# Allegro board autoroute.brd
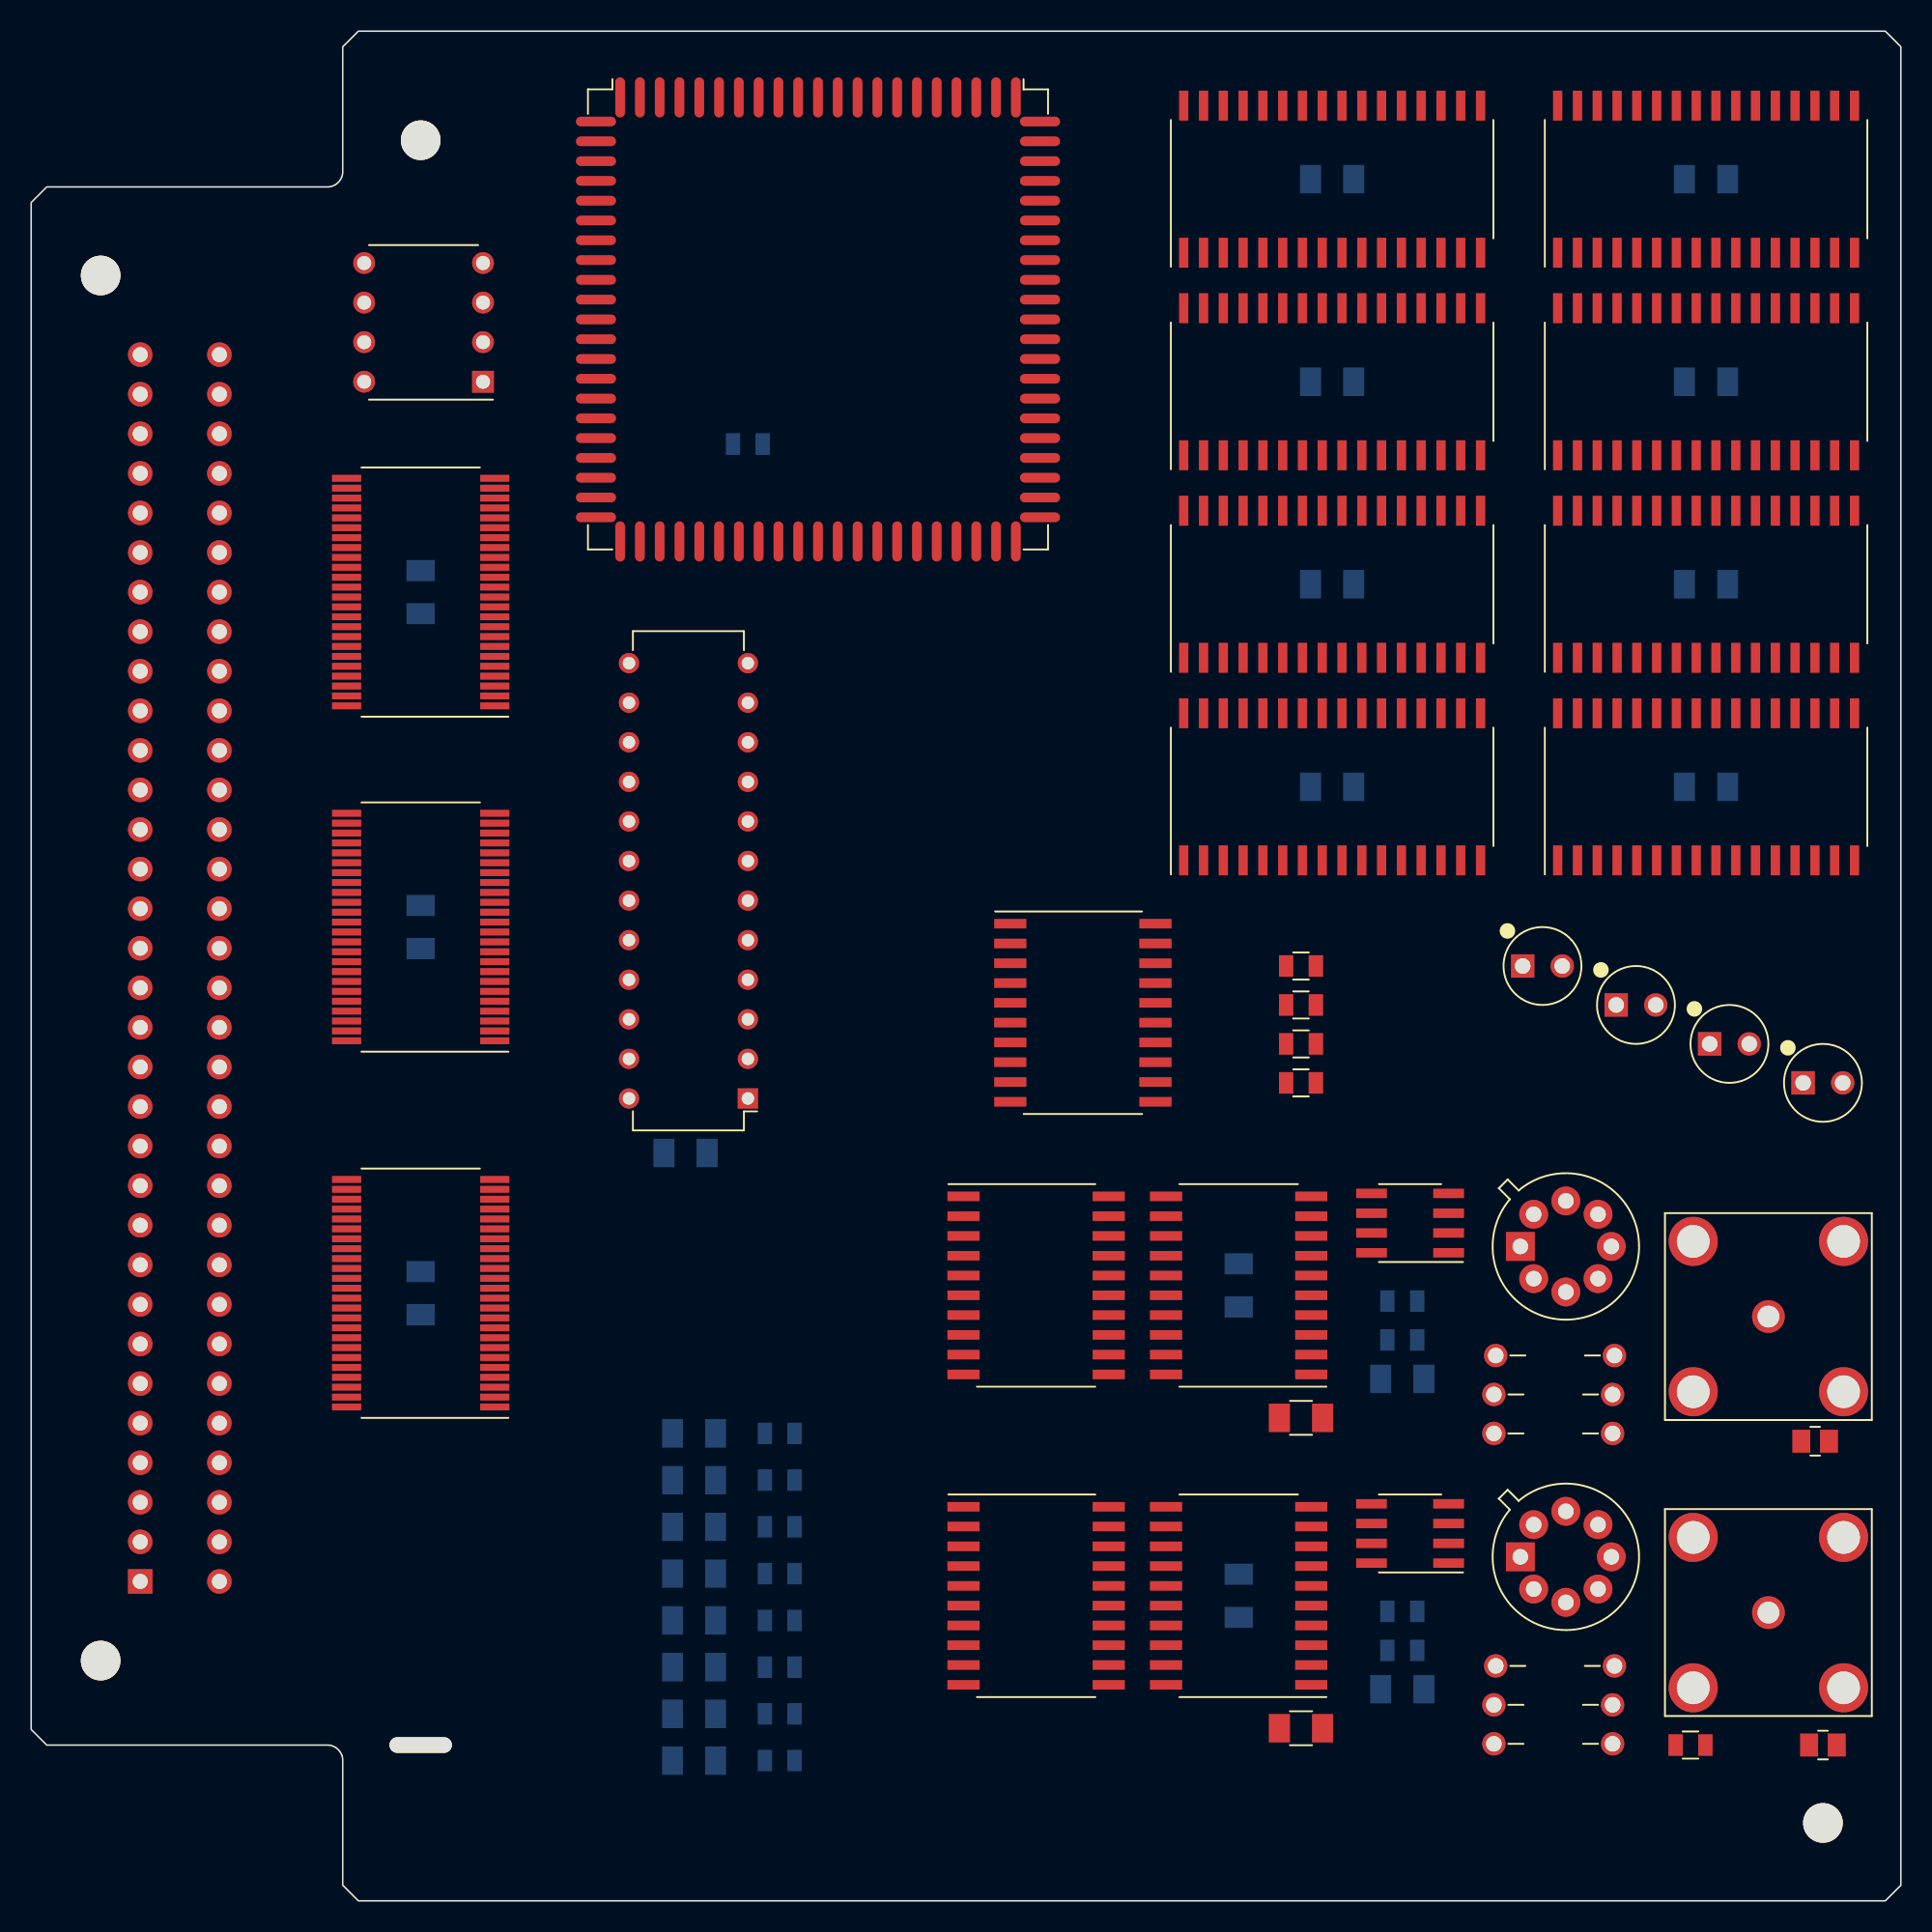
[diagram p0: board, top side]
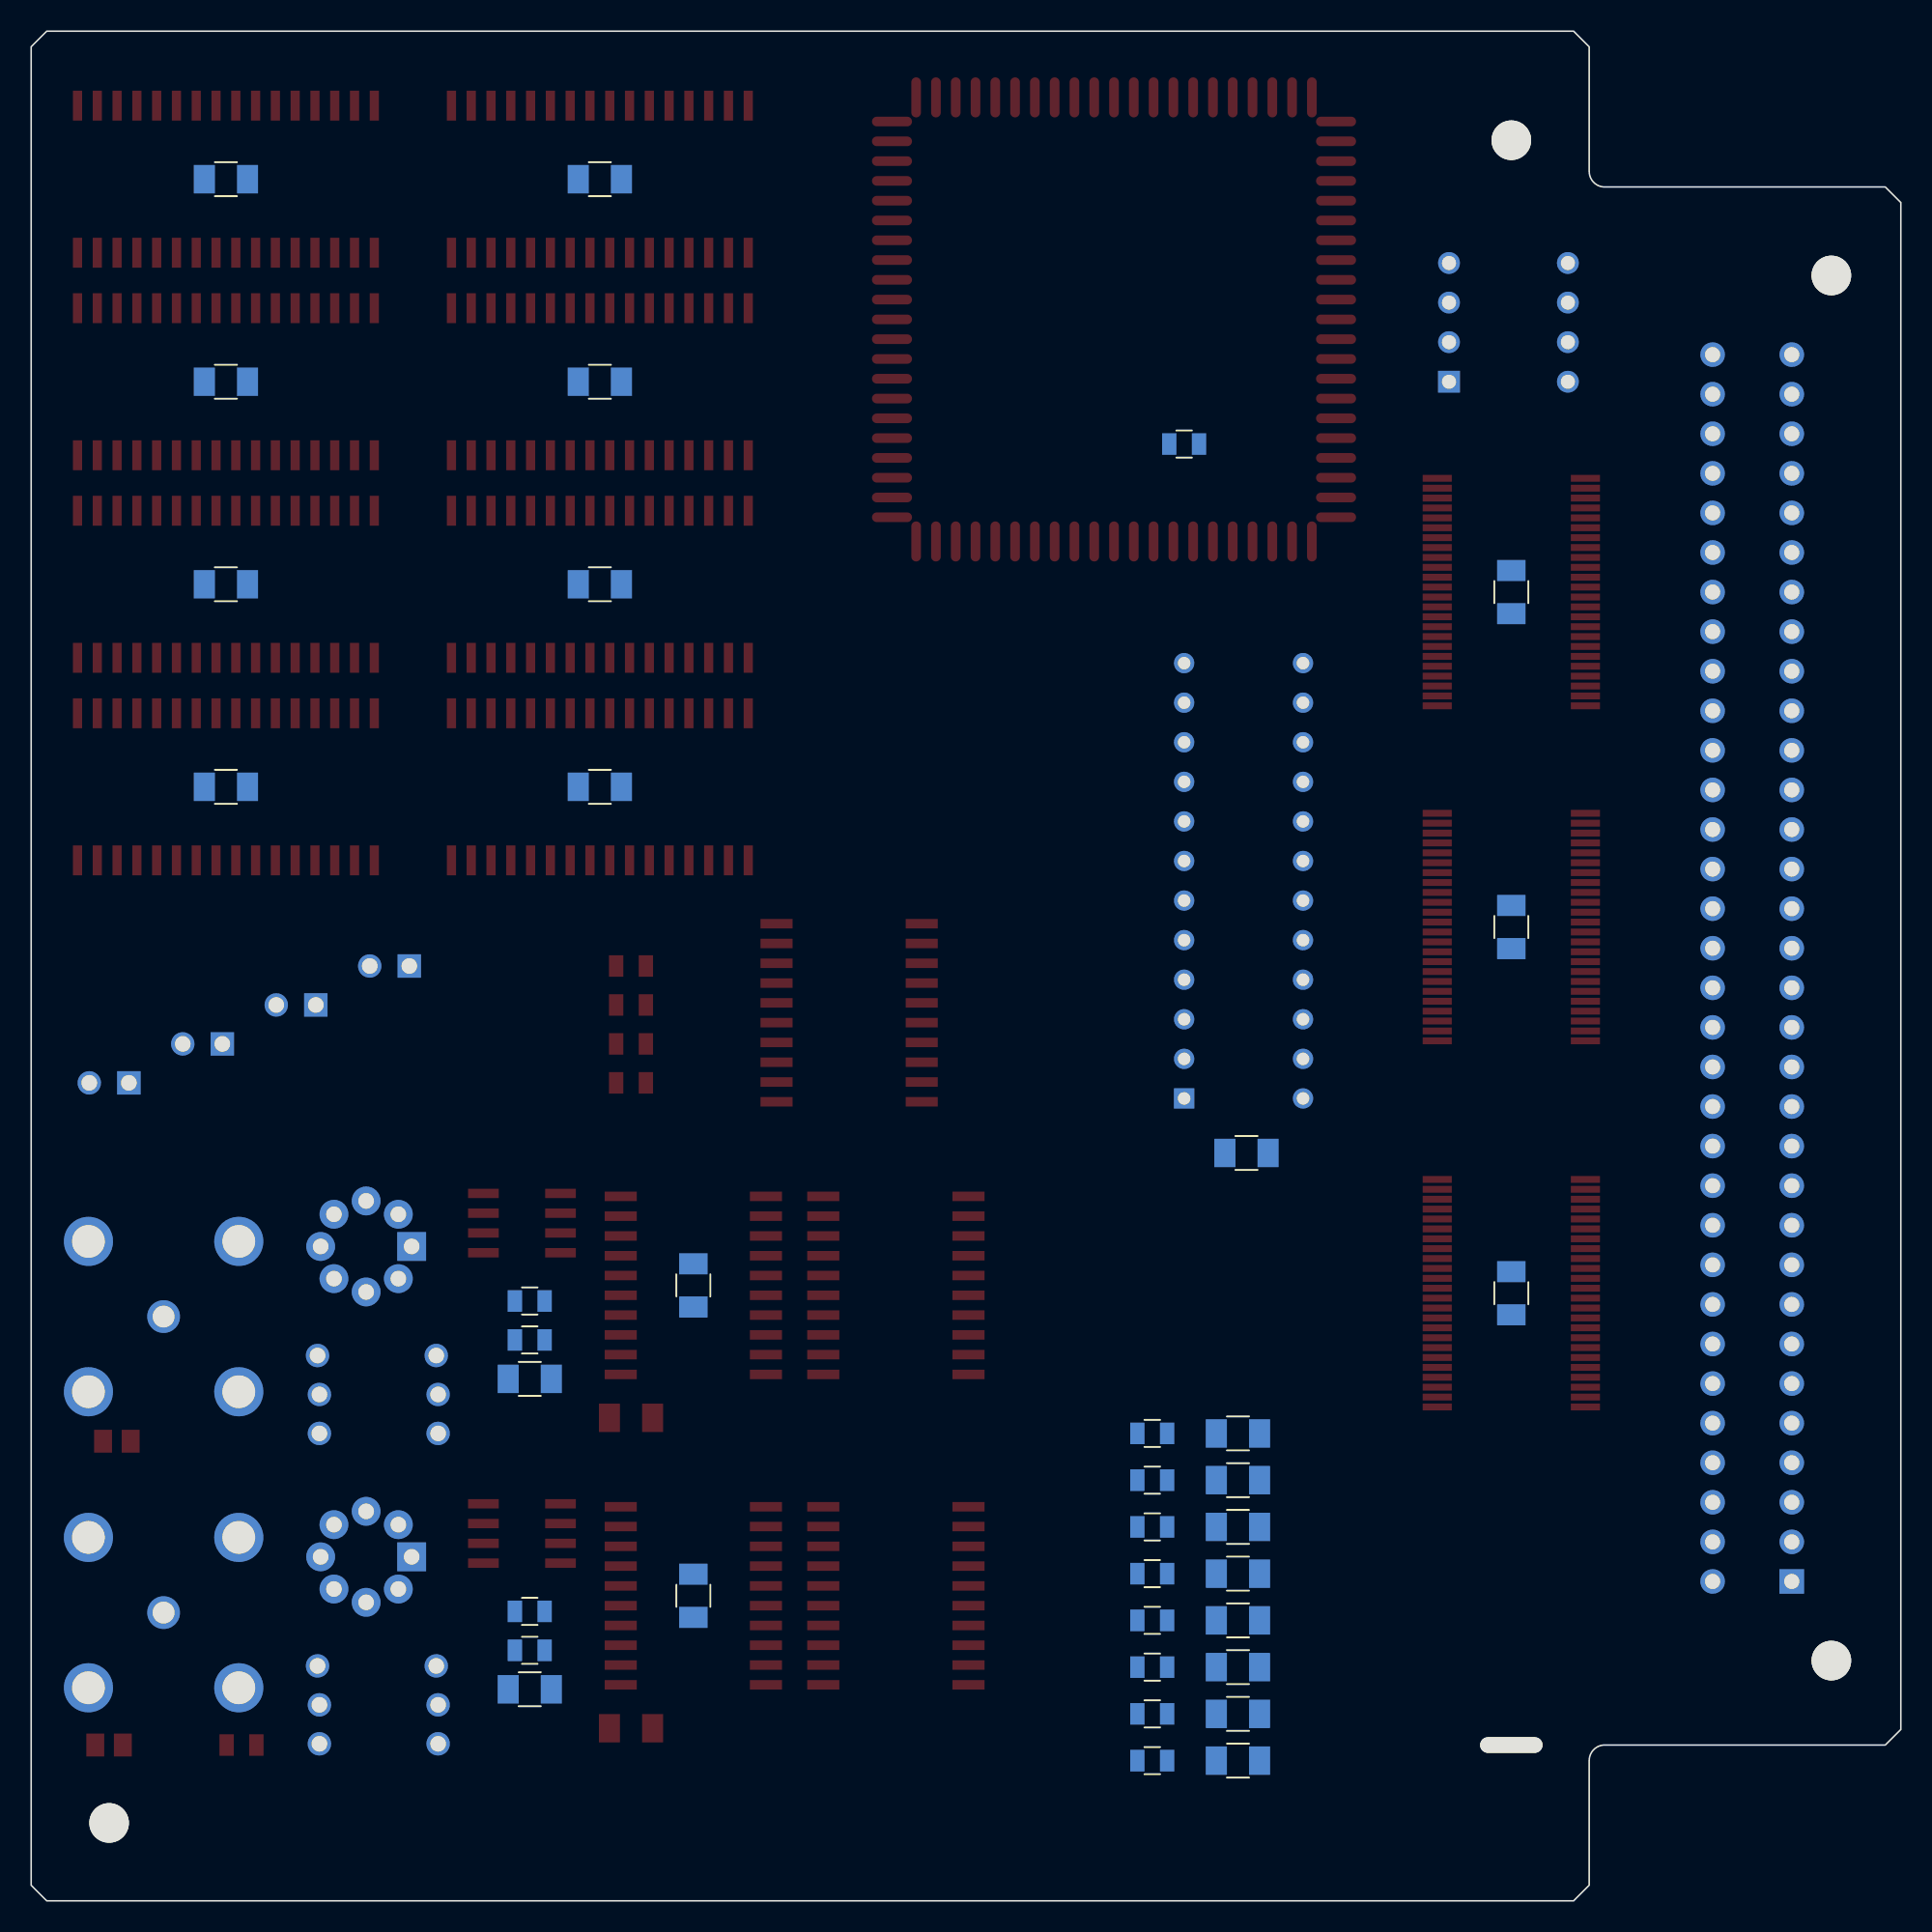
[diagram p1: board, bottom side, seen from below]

Outline 120 x 120 mm; copper layers: TOP, GND1, VCC1, VCC2, GND2, BOTTOM. Coordinates in mm from the lower left corner of the outline.

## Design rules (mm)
constraint set DEFAULT: min track width 0.15, pair gap 0.15
net group SYNC: nets VCLKA VCLKC
net group MEMORY[0..28]: nets MEMORY.RA0 MEMORY.RA1 MEMORY.RA2 MEMORY.RA3 MEMORY.RA4 MEMORY.RA5 MEMORY.RA6 MEMORY.RA7 MEMORY.RA8 MEMORY.RA9 MEMORY.RA10 MEMORY.RA11 MEMORY.RA12 MEMORY.RA13 MEMORY.RA14 MEMORY.RA15 MEMORY.RCS0 MEMORY.RCS1 MEMORY.RCS2 MEMORY.RCS3 MEMORY.RD0 MEMORY.RD1 MEMORY.RD2 MEMORY.RD3 MEMORY.RD4 MEMORY.RD5 MEMORY.RD6 MEMORY.RD7 MEMORY.RWE
net group POWER: nets AGND GND_EARTH V12N V+12
net group VDNETS: nets VD0 VD1 VD2 VD3 VD4 VD5 VD6 VD7
nets with their own width: min track width 0.4; nets GND VCC

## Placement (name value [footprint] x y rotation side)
C1  0.1uF  [CAPC3216X110N]  25 39 90 bottom
C2  0.1uF  [CAPC3216X110N]  42 48 0 bottom
C3  0.1uF  [CAPC3216X110N]  25 62.5 90 bottom
C4  0.1uF  [CAPC3216X110N]  25 84 90 bottom
C5  47PF  [CAPC2012X110N]  114.5 29.5 0 top
C6  47PF  [CAPC2012X110N]  115 10 0 top
C7  0.01u  [CAPC3216X110N]  81.5 31 0 top
C8  0.01u  [CAPC3216X110N]  77.5 39.5 90 bottom
C9  0.1u  [CAPC3216X110N]  88 33.5 180 bottom
C10  0.01u  [CAPC3216X110N]  81.5 11.08 0 top
C11  0.01u  [CAPC3216X110N]  77.5 19.58 90 bottom
C12  0.1u  [CAPC3216X110N]  88 13.58 180 bottom
C13  330p  [CAPC3216X110N]  42.55 12 180 bottom
C14  330p  [CAPC3216X110N]  42.55 18 180 bottom
C15  330p  [CAPC3216X110N]  42.55 24 180 bottom
C16  330p  [CAPC3216X110N]  42.55 30 180 bottom
C17  330p  [CAPC3216X110N]  42.55 9 180 bottom
C18  330p  [CAPC3216X110N]  42.55 15 180 bottom
C19  330p  [CAPC3216X110N]  42.55 21 180 bottom
C20  330p  [CAPC3216X110N]  42.55 27 180 bottom
C21  0.1uF  [CAPC3216X110N]  83.5 71.5 0 bottom
C22  0.1uF  [CAPC3216X110N]  107.5 71.5 0 bottom
C23  0.1uF  [CAPC3216X110N]  83.5 84.5 0 bottom
C24  0.1uF  [CAPC3216X110N]  107.5 84.5 0 bottom
C25  0.1uF  [CAPC3216X110N]  83.5 97.5 0 bottom
C26  0.1uF  [CAPC3216X110N]  107.5 97.5 0 bottom
C27  0.1uF  [CAPC3216X110N]  107.5 110.5 0 bottom
C28  0.1uF  [CAPC3216X110N]  83.5 110.5 0 bottom
D1  LED  [LEDRD254W00D500H860P]  97 60 0 top
D2  LED  [LEDRD254W00D500H860P]  103 57.5 0 top
D3  LED  [LEDRD254W00D500H860P]  109 55 0 top
D4  LED  [LEDRD254W00D500H860P]  115 52.5 0 top
J1  CON64  [DIN64]  7 20.5 0 top
J2  BNC  [CONNEX_112659]  111.5 37.5 0 top
J3  BNC  [CONNEX_112659]  111.5 18.5 0 top
L1  47u  [INDAD762W79L381D254P]  94 35 0 top
L2  47u  [INDAD762W79L381D254P]  94 15.08 0 top
L3  47u  [INDAD762W79L381D254P]  101.5 32.5 180 top
L4  47u  [INDAD762W79L381D254P]  101.5 30 180 top
L5  47u  [INDAD762W79L381D254P]  101.5 12.58 180 top
L6  47u  [INDAD762W79L381D254P]  101.5 10.08 180 top
NOREF  -  []  19.78 110.37 0 top
NOREF#2  -  []  25 10 0 top
NOREF#3  -  []  192.64 154.78 0 top
NOREF#4  -  []  25 10 0 top
NOREF#5  -  []  23 0 90 top
NOREF#6  -  []  119.52 119.48 0 top
NOREF#7  -  []  -74.06 -89.06 0 top
NOREF#8  -  []  20 6.38 0 top
NOREF#9  -  []  25 10 90 top
NOREF#10  -  [unnamed#2]  25 10 0 top
NOREF#11  -  []  25 10 90 top
NOREF#12  -  []  25 10 90 top
NOREF#13  -  []  115 5 90 top
NOREF#14  -  []  0 20.43 0 top
R1  150  [RESC2012X60N]  81.5 60 0 top
R2  150  [RESC2012X60N]  81.5 57.5 0 top
R3  150  [RESC2012X60N]  81.5 55 0 top
R4  150  [RESC2012X60N]  81.5 52.5 0 top
R5  2K  [RESC2012X60N]  46 93.5 0 bottom
R6  100  [RESC2012X60N]  88 38.5 180 bottom
R7  100  [RESC2012X60N]  88 36 180 bottom
R8  100  [RESC2012X60N]  88 18.58 180 bottom
R9  100  [RESC2012X60N]  88 16.08 180 bottom
R10  10K  [RESC2012X60N]  48.05 12 0 bottom
R11  10K  [RESC2012X60N]  48.05 18 0 bottom
R12  10K  [RESC2012X60N]  48.05 24 0 bottom
R13  10K  [RESC2012X60N]  48.05 30 0 bottom
R14  10K  [RESC2012X60N]  48.05 9 0 bottom
R15  10K  [RESC2012X60N]  48.05 15 0 bottom
R16  10K  [RESC2012X60N]  48.05 21 0 bottom
R17  10K  [RESC2012X60N]  48.05 27 0 bottom
R18  10K  [RESC2012X60N]  106.5 10 0 top
U1  FCT16245  [SOP63P1035X279-48N]  25 39 90 top
U2  20L10  [DIP763W46P254L3204H508Q24P]  46 51.5 90 top
U3  FCT16245  [SOP63P1035X279-48N]  25 62.5 90 top
U4  FCT16245  [SOP63P1035X279-48N]  25 84 90 top
U5  EPF8282A_LCC  [PLCC127P3022X3022X457-84N]  50.5 101.5 270 top
U6  74ACT574  [SOIC127P1034X264-20N]  67.5 57 270 top
U7  EPC1064  [DIP763W46P254L991H419Q8P]  29 97.5 90 top
U8  TLC5602A  [SOIC127P1034X264-20N]  77.5 39.5 90 top
U9  TLE2037A  [TO292P469H584-8P]  98.5 42 0 top
U10  DG419AK  [SOIC127P600X175-8N]  88.5 43.5 90 top
U11  TLC5602A  [SOIC127P1034X264-20N]  77.5 19.58 90 top
U12  TLE2037A  [TO292P469H584-8P]  98.5 22.08 0 top
U13  DG419AK  [SOIC127P600X175-8N]  88.5 23.58 90 top
U14  74ACT574  [SOIC127P1034X264-20N]  64.5 39.5 270 top
U15  74ACT574  [SOIC127P1034X264-20N]  64.5 19.58 270 top
U16  TC55B4257  [SOIC127P1032X265-32N]  83.5 71.5 0 top
U17  TC55B4257  [SOIC127P1032X265-32N]  83.5 84.5 0 top
U18  TC55B4257  [SOIC127P1032X265-32N]  83.5 97.5 0 top
U19  TC55B4257  [SOIC127P1032X265-32N]  83.5 110.5 0 top
U20  TC55B4257  [SOIC127P1032X265-32N]  107.5 71.5 0 top
U21  TC55B4257  [SOIC127P1032X265-32N]  107.5 84.5 0 top
U22  TC55B4257  [SOIC127P1032X265-32N]  107.5 97.5 0 top
U23  TC55B4257  [SOIC127P1032X265-32N]  107.5 110.5 0 top

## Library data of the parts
C1-C4 C13-C20 = CAP NP
C5 C7-C9 = CAP NP: room: CHAN1
C6 C10-C12 = CAP NP: room: CHAN2
C21-C28 = CAP NP: room: MEM
D1-D4 = PHOTODIODE_0
J1 = CON64
J2 = BNC: room: CHAN1
J3 = BNC: room: CHAN2
L1 L3 L4 = INDUCTOR: room: CHAN1
L2 L5 L6 = INDUCTOR: room: CHAN2
R1-R4 = R: room: LED
R5 R10-R17 = R
R6 R7 = R: room: CHAN1
R8 R9 R18 = R: room: CHAN2
U1 U3 U4 = FCT16245
U2 = 20L10: alternate symbols: (T:SOIC24;B:SOIC24_PE)
U5 = EPF8282A/LCC
U6 = 74ACT574: room: LED
U7 = EPC1064
U8 = TLC5602A: room: CHAN1
U9 = TLE2037A: room: CHAN1
U10 = DG419AK: room: CHAN1
U11 = TLC5602A: room: CHAN2
U12 = TLE2037A: room: CHAN2
U13 = DG419AK: room: CHAN2
U14 = 74ACT574: room: CHAN1
U15 = 74ACT574: room: CHAN2
U16-U23 = TC55B4257: room: MEM

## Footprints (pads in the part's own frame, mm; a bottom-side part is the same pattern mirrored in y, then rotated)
CAPC2012X110N
  rect 1.15x1.47 smd: 1(-0.885,0) 2(0.885,0)
CAPC3216X110N
  rect 1.35x1.82 smd: 1(-1.385,0) 2(1.385,0)
CONNEX_112659
  round 2.1 hole 1.4: 1(0,0)
  round 3.15 hole 2.1: 2(-4.825,4.825) 3(4.825,4.825) 4(4.825,-4.825) 5(-4.825,-4.825)
DIN64
  round 2.54 hole 2.794 unplated: (-2.54,83.82) (-2.54,-5.08)
  rect 1.575x1.575 hole 0.965: 1(0,0)
  round 1.575 hole 0.965: 2(0,2.54) 3(0,5.08) 4(0,7.62) 5(0,10.16) 6(0,12.7) 7(0,15.24) 8(0,17.78) 9(0,20.32) 10(0,22.86) 11(0,25.4) 12(0,27.94) 13(0,30.48) 14(0,33.02) 15(0,35.56) 16(0,38.1) 17(0,40.64) 18(0,43.18) 19(0,45.72) 20(0,48.26) 21(0,50.8) 22(0,53.34) 23(0,55.88) 24(0,58.42) 25(0,60.96) 26(0,63.5) 27(0,66.04) 28(0,68.58) 29(0,71.12) 30(0,73.66) 31(0,76.2) 32(0,78.74) 33(5.08,0) 34(5.08,2.54) 35(5.08,5.08) 36(5.08,7.62) 37(5.08,10.16) 38(5.08,12.7) 39(5.08,15.24) 40(5.08,17.78) 41(5.08,20.32) 42(5.08,22.86) 43(5.08,25.4) 44(5.08,27.94) 45(5.08,30.48) 46(5.08,33.02) 47(5.08,35.56) 48(5.08,38.1) 49(5.08,40.64) 50(5.08,43.18) 51(5.08,45.72) 52(5.08,48.26) 53(5.08,50.8) 54(5.08,53.34) 55(5.08,55.88) 56(5.08,58.42) 57(5.08,60.96) 58(5.08,63.5) 59(5.08,66.04) 60(5.08,68.58) 61(5.08,71.12) 62(5.08,73.66) 63(5.08,76.2) 64(5.08,78.74)
DIP763W46P254L991H419Q8P
  rect 1.4x1.4 hole 0.9: 1(0,0)
  round 1.4 hole 0.9: 2(2.54,0) 3(5.08,0) 4(7.62,0) 5(7.62,7.63) 6(5.08,7.63) 7(2.54,7.63) 8(0,7.63)
DIP763W46P254L3204H508Q24P
  rect 1.3x1.3 hole 0.8: 1(0,0)
  round 1.3 hole 0.8: 2(2.54,0) 3(5.08,0) 4(7.62,0) 5(10.16,0) 6(12.7,0) 7(15.24,0) 8(17.78,0) 9(20.32,0) 10(22.86,0) 11(25.4,0) 12(27.94,0) 13(27.94,7.63) 14(25.4,7.63) 15(22.86,7.63) 16(20.32,7.63) 17(17.78,7.63) 18(15.24,7.63) 19(12.7,7.63) 20(10.16,7.63) 21(7.62,7.63) 22(5.08,7.63) 23(2.54,7.63) 24(0,7.63)
INDAD762W79L381D254P
  round 1.5 hole 1: 1(0,0) 2(7.62,0)
LEDRD254W00D500H860P
  round 1.5 hole 1: A(1.27,0)
  rect 1.5x1.5 hole 1: C(-1.27,0)
PLCC127P3022X3022X457-84N
  oval 2.57x0.62 smd: 1(-14.25,0) 2(-14.25,-1.27) 3(-14.25,-2.54) 4(-14.25,-3.81) 5(-14.25,-5.08) 6(-14.25,-6.35) 7(-14.25,-7.62) 8(-14.25,-8.89) 9(-14.25,-10.16) 10(-14.25,-11.43) 11(-14.25,-12.7) 33(14.25,-12.7) 34(14.25,-11.43) 35(14.25,-10.16) 36(14.25,-8.89) 37(14.25,-7.62) 38(14.25,-6.35) 39(14.25,-5.08) 40(14.25,-3.81) 41(14.25,-2.54) 42(14.25,-1.27) 43(14.25,0) 44(14.25,1.27) 45(14.25,2.54) 46(14.25,3.81) 47(14.25,5.08) 48(14.25,6.35) 49(14.25,7.62) 50(14.25,8.89) 51(14.25,10.16) 52(14.25,11.43) 53(14.25,12.7) 75(-14.25,12.7) 76(-14.25,11.43) 77(-14.25,10.16) 78(-14.25,8.89) 79(-14.25,7.62) 80(-14.25,6.35) 81(-14.25,5.08) 82(-14.25,3.81) 83(-14.25,2.54) 84(-14.25,1.27)
  oval 0.62x2.57 smd: 12(-12.7,-14.25) 13(-11.43,-14.25) 14(-10.16,-14.25) 15(-8.89,-14.25) 16(-7.62,-14.25) 17(-6.35,-14.25) 18(-5.08,-14.25) 19(-3.81,-14.25) 20(-2.54,-14.25) 21(-1.27,-14.25) 22(0,-14.25) 23(1.27,-14.25) 24(2.54,-14.25) 25(3.81,-14.25) 26(5.08,-14.25) 27(6.35,-14.25) 28(7.62,-14.25) 29(8.89,-14.25) 30(10.16,-14.25) 31(11.43,-14.25) 32(12.7,-14.25) 54(12.7,14.25) 55(11.43,14.25) 56(10.16,14.25) 57(8.89,14.25) 58(7.62,14.25) 59(6.35,14.25) 60(5.08,14.25) 61(3.81,14.25) 62(2.54,14.25) 63(1.27,14.25) 64(0,14.25) 65(-1.27,14.25) 66(-2.54,14.25) 67(-3.81,14.25) 68(-5.08,14.25) 69(-6.35,14.25) 70(-7.62,14.25) 71(-8.89,14.25) 72(-10.16,14.25) 73(-11.43,14.25) 74(-12.7,14.25)
RESC2012X60N
  rect 0.92x1.38 smd: 1(-0.955,0) 2(0.955,0)
SOIC127P600X175-8N
  rect 0.6x1.97 smd: 1(-1.905,-2.475) 2(-0.635,-2.475) 3(0.635,-2.475) 4(1.905,-2.475) 5(1.905,2.475) 6(0.635,2.475) 7(-0.635,2.475) 8(-1.905,2.475)
SOIC127P1032X265-32N
  rect 0.59x1.92 smd: 1(-9.525,-4.72) 2(-8.255,-4.72) 3(-6.985,-4.72) 4(-5.715,-4.72) 5(-4.445,-4.72) 6(-3.175,-4.72) 7(-1.905,-4.72) 8(-0.635,-4.72) 9(0.635,-4.72) 10(1.905,-4.72) 11(3.175,-4.72) 12(4.445,-4.72) 13(5.715,-4.72) 14(6.985,-4.72) 15(8.255,-4.72) 16(9.525,-4.72) 17(9.525,4.72) 18(8.255,4.72) 19(6.985,4.72) 20(5.715,4.72) 21(4.445,4.72) 22(3.175,4.72) 23(1.905,4.72) 24(0.635,4.72) 25(-0.635,4.72) 26(-1.905,4.72) 27(-3.175,4.72) 28(-4.445,4.72) 29(-5.715,4.72) 30(-6.985,4.72) 31(-8.255,4.72) 32(-9.525,4.72)
SOIC127P1034X264-20N
  rect 0.61x2.06 smd: 1(-5.715,-4.66) 2(-4.445,-4.66) 3(-3.175,-4.66) 4(-1.905,-4.66) 5(-0.635,-4.66) 6(0.635,-4.66) 7(1.905,-4.66) 8(3.175,-4.66) 9(4.445,-4.66) 10(5.715,-4.66) 11(5.715,4.66) 12(4.445,4.66) 13(3.175,4.66) 14(1.905,4.66) 15(0.635,4.66) 16(-0.635,4.66) 17(-1.905,4.66) 18(-3.175,4.66) 19(-4.445,4.66) 20(-5.715,4.66)
SOP63P1035X279-48N
  rect 0.44x1.87 smd: 1(-7.302,-4.755) 2(-6.668,-4.755) 3(-6.032,-4.755) 4(-5.398,-4.755) 5(-4.762,-4.755) 6(-4.128,-4.755) 7(-3.492,-4.755) 8(-2.858,-4.755) 9(-2.222,-4.755) 10(-1.588,-4.755) 11(-0.952,-4.755) 12(-0.318,-4.755) 13(0.318,-4.755) 14(0.952,-4.755) 15(1.588,-4.755) 16(2.222,-4.755) 17(2.858,-4.755) 18(3.492,-4.755) 19(4.128,-4.755) 20(4.762,-4.755) 21(5.398,-4.755) 22(6.032,-4.755) 23(6.668,-4.755) 24(7.302,-4.755) 25(7.302,4.755) 26(6.668,4.755) 27(6.032,4.755) 28(5.398,4.755) 29(4.762,4.755) 30(4.128,4.755) 31(3.492,4.755) 32(2.858,4.755) 33(2.222,4.755) 34(1.588,4.755) 35(0.952,4.755) 36(0.318,4.755) 37(-0.318,4.755) 38(-0.952,4.755) 39(-1.588,4.755) 40(-2.222,4.755) 41(-2.858,4.755) 42(-3.492,4.755) 43(-4.128,4.755) 44(-4.762,4.755) 45(-5.398,4.755) 46(-6.032,4.755) 47(-6.668,4.755) 48(-7.302,4.755)
TO292P469H584-8P
  rect 1.85x1.85 hole 1: 1(-2.921,0)
  round 1.85 hole 1: 2(-2.066,-2.066) 3(0,-2.921) 4(2.066,-2.066) 5(2.921,0) 6(2.066,2.066) 7(0,2.921) 8(-2.066,2.066)
unnamed#2
  round 2.54 hole 2.794 unplated: (0,103) (90,-5)
  oval 4x1 hole 5x1.5 unplated: (0,0)

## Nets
AGND: C8.2 C9.2 C11.2 C12.2 J1.34 J1.35 J1.36 U8.3 U8.7 U8.10 U10.3 U11.3 U11.7 U11.10 U13.3
GND: C1.2 C2.2 C3.2 C4.2 C7.2 C10.2 C13.2 C14.2 C15.2 C16.2 C17.2 C18.2 C19.2 C20.2 C21.2 C22.2 C23.2 C24.2 C25.2 C26.2 C27.2 C28.2 J1.1 J1.2 J1.3 J1.33 R18.2 U1.4 U1.10 U1.15 U1.21 U1.24 U1.25(G\) U1.28 U1.34 U1.39 U1.45 U2.11 U2.12 U2.13 U3.4 U3.10 U3.15 U3.21 U3.24 U3.25(G\) U3.28 U3.34 U3.39 U3.45 U4.1 U4.4 U4.10 U4.15 U4.21 U4.28 U4.34 U4.39 U4.45 U4.48 U5.5 U5.26 U5.47 U5.53 U5.68 U5.74 U5.75 U6.1 U6.10 U7.5 U8.1 U8.20 U11.1 U11.20 U14.1 U14.10 U15.1 U15.10 U16.9 U16.25 U16.27 U17.9 U17.25 U17.27 U18.9 U18.25 U18.27 U19.9 U19.25 U19.27 U20.9 U20.25 U20.27 U21.9 U21.25 U21.27 U22.9 U22.25 U22.27 U23.9 U23.25 U23.27
GND_EARTH: C5.2 C6.2 J2.2 J2.3 J2.4 J2.5(GND5) J3.2 J3.3 J3.4 J3.5(GND5)
V12N: J1.31 J1.32 U9.4(V-) U10.7 U12.4(V-) U13.7
VCC: C1.1 C2.1 C3.1 C4.1 C7.1 C10.1 C21.1 C22.1 C23.1 C24.1 C25.1 C26.1 C27.1 C28.1 D1.A D2.A D3.A D4.A J1.29 J1.30 J1.62 L4.1 L6.1 U1.7 U1.18 U1.31 U1.42 U2.24(VCC) U3.7 U3.18 U3.31 U3.42 U4.7 U4.18 U4.31 U4.42 U5.17 U5.38 U5.59 U5.80 U6.20 U7.7 U7.8 U8.2 U8.9(VD2) U11.2 U11.9(VD2) U14.20 U15.20 U16.8 U16.24 U17.8 U17.24 U18.8 U18.24 U19.8 U19.24 U20.8 U20.24 U21.8 U21.24 U22.8 U22.24 U23.8 U23.24
A0: J1.54 U4.36
A1: J1.55 U4.35
A2: J1.56 U4.33
A3: J1.57 U4.32
A4: J1.58 U4.30
A5: J1.59 U4.29
A6: J1.60 U4.27
A7: J1.61 U4.26
A8: J1.13 U3.47
A9: J1.14 U3.46
A10: J1.15 U3.44
A11: J1.16 U3.43
A12: J1.17 U3.41
A13: J1.18 U3.40
A14: J1.19 U3.38
A15: J1.20 U3.37
A16: J1.37 U1.47
A17: J1.38 U1.46
A18: J1.39 U1.44 U2.6
A19: J1.40 U1.43 U2.5
A20: J1.41 U1.41 U2.4
A21: J1.42 U1.40 U2.3
A22: J1.43 U1.38 U2.2
A23: J1.44 U1.37 U2.1
AEN: J1.47 U2.8
BA0: U1.13 U3.13 U4.2 U5.6
BA1: U1.14 U3.14 U4.3 U5.7
BA2: U1.16 U3.16 U4.5 U5.8
BA3: U1.17 U3.17 U4.6 U5.9
BA4: U1.19 U3.19 U4.8
BA5: U1.20 U3.20 U4.9
BA6: U1.22 U3.22 U4.11
BA7: U1.23 U3.23 U4.12
BD0: U4.23 U5.25
BD1: U4.22 U5.24
BD2: U4.20 U5.23
BD3: U4.19 U5.22
BD4: U4.17 U5.21
BD5: U4.16 U5.20
BD6: U4.14 U5.19
BD7: U4.13 U5.18
BD8: U1.12 U3.2
BD9: U1.11 U3.3
BD10: U1.9 U3.5
BD11: U1.8 U3.6
BD12: U1.6 U3.8
BD13: U1.5 U3.9
BD14: U1.3 U3.11
BD15: U1.2 U3.12
BNC2: C5.1 J2.1 L1.2
BNC3: C6.1 J3.1 L2.2
BRD: U2.16 U5.73
BRESET: U2.15 U5.12
BWR: U2.17 U5.54
D0: J1.28 U3.26 U4.37
D1: J1.27 U3.27 U4.38
D2: J1.26 U3.29 U4.40
D3: J1.25 U3.30 U4.41
D4: J1.24 U3.32 U4.43
D5: J1.23 U3.33 U4.44
D6: J1.22 U3.35 U4.46
D7: J1.21 U3.36 U4.47
D8: J1.4 U1.36
D9: J1.5 U1.35
D10: J1.6 U1.33
D11: J1.7 U1.32
D12: J1.8 U1.30
D13: J1.9 U1.29
D14: J1.10 U1.27
D15: J1.11 U1.26
DATA: U5.14 U7.1
DCLK: U5.10 U7.2
DDIR: U1.48 U2.20 U3.48 U4.25(G\)
DEN: U1.1 U2.21 U4.24
DHEN: U2.22 U3.1
FPGA: U2.18 U5.30
GAIN: U5.28 U10.6 U13.6
HS: U2.19 U5.29
LED1: D1.C(CATHODE) R1.2
LED2: D2.C(CATHODE) R2.2
LED3: D3.C(CATHODE) R3.2
LED4: D4.C(CATHODE) R4.2
MCLK: J1.52 U5.31
MEMORY.RA0: U5.79 U16.5 U17.5 U18.5 U19.5 U20.5 U21.5 U22.5 U23.5
MEMORY.RA1: U5.78 U16.4 U17.4 U18.4 U19.4 U20.4 U21.4 U22.4 U23.4
MEMORY.RA2: U5.77 U16.3 U17.3 U18.3 U19.3 U20.3 U21.3 U22.3 U23.3
MEMORY.RA3: U5.76 U16.2 U17.2 U18.2 U19.2 U20.2 U21.2 U22.2 U23.2
MEMORY.RA4: U5.71 U16.32 U17.32 U18.32 U19.32 U20.32 U21.32 U22.32 U23.32
MEMORY.RA5: U5.70 U16.31 U17.31 U18.31 U19.31 U20.31 U21.31 U22.31 U23.31
MEMORY.RA6: U5.69 U16.30 U17.30 U18.30 U19.30 U20.30 U21.30 U22.30 U23.30
MEMORY.RA7: U5.67 U16.29 U17.29 U18.29 U19.29 U20.29 U21.29 U22.29 U23.29
MEMORY.RA8: U5.66 U16.28 U17.28 U18.28 U19.28 U20.28 U21.28 U22.28 U23.28
MEMORY.RA9: U5.65 U16.22 U17.22 U18.22 U19.22 U20.22 U21.22 U22.22 U23.22
MEMORY.RA10: U5.64 U16.21 U17.21 U18.21 U19.21 U20.21 U21.21 U22.21 U23.21
MEMORY.RA11: U5.63 U16.20 U17.20 U18.20 U19.20 U20.20 U21.20 U22.20 U23.20
MEMORY.RA12: U5.62 U16.19 U17.19 U18.19 U19.19 U20.19 U21.19 U22.19 U23.19
MEMORY.RA13: U5.61 U16.18 U17.18 U18.18 U19.18 U20.18 U21.18 U22.18 U23.18
MEMORY.RA14: U5.60 U16.15 U17.15 U18.15 U19.15 U20.15 U21.15 U22.15 U23.15
MEMORY.RA15: U5.58 U16.14 U17.14 U18.14 U19.14 U20.14 U21.14 U22.14 U23.14
MEMORY.RCS0: U5.51 U16.6 U17.6
MEMORY.RCS1: U5.50 U18.6 U19.6
MEMORY.RCS2: U5.49 U20.6 U21.6
MEMORY.RCS3: U5.48 U22.6 U23.6
MEMORY.RD0: U5.81 U16.7 U18.7 U20.7 U22.7
MEMORY.RD1: U5.82 U16.10 U18.10 U20.10 U22.10
MEMORY.RD2: U5.83 U16.23 U18.23 U20.23 U22.23
MEMORY.RD3: U5.84 U16.26 U18.26 U20.26 U22.26
MEMORY.RD4: U5.1 U17.7 U19.7 U21.7 U23.7
MEMORY.RD5: U5.2 U17.10 U19.10 U21.10 U23.10
MEMORY.RD6: U5.3 U17.23 U19.23 U21.23 U23.23
MEMORY.RD7: U5.4 U17.26 U19.26 U21.26 U23.26
MEMORY.RWE: U5.56 U16.11(W\E\) U17.11(W\E\) U18.11(W\E\) U19.11(W\E\) U20.11(W\E\) U21.11(W\E\) U22.11(W\E\) U23.11(W\E\)
MRD: J1.46 U2.9
MWR: J1.45 U2.10
N00036_DATA_DAAMP: L4.2 R6.1 R7.1 U8.5 U8.8 U10.5(VL)
N00036_DATA_DAAMP1: L6.2 R8.1 R9.1 U11.5 U11.8 U13.5(VL)
N00038_DATA_DAAMP: C8.1 L3.2 U8.4
N00038_DATA_DAAMP1: C11.1 L5.2 U11.4
N00044_DATA_DAAMP: U9.2 U10.1
N00044_DATA_DAAMP1: U12.2 U13.1
N00060_DATA_DAAMP: U8.6 U9.3
N00060_DATA_DAAMP1: U11.6 U12.3
N282866_DATA_DAAMP: R6.2 U10.8
N282866_DATA_DAAMP1: R8.2 U13.8
N282912_DATA_DAAMP: R7.2 U10.2
N282912_DATA_DAAMP1: R9.2 U13.2
NCS: U5.11 U7.4
OE: U5.32 U7.3(OE)
OUTA: L1.1 U9.6
OUTB: L2.1 U12.6
Q0: R1.1 U6.18
Q1: R2.1 U6.16
Q2: R3.1 U6.14
Q3: R4.1 U6.12(Q8)
RDY: J1.50 U2.23
RESET: J1.53 U5.15
SEL: U2.14 U5.13
V+12: C9.1 C12.1 J1.63 J1.64 U9.7 U10.4 U12.7 U13.4
VCLKA: U5.34 U8.11 U14.11
VCLKC: R5.2 U11.11 U15.11
VD0: R13.2 U5.39 U6.2 U14.2 U15.2
VD1: R17.2 U5.40 U6.3 U14.3 U15.3
VD2: R12.2 U5.41 U6.4 U14.4 U15.4
VD3: R16.2 U5.42 U6.5 U14.5 U15.5
VD4: R11.2 U5.43 U6.6 U14.6 U15.6
VD5: R15.2 U5.44 U6.7 U14.7 U15.7
VD6: R10.2 U5.45 U6.8 U14.8 U15.8
VD7: R14.2 U5.46(VD7) U6.9 U14.9 U15.9
VREF: L3.1 L5.1 R18.1
WAIT: J1.51 U5.33
WSTAT: U5.57 U6.11
N14843: C19.1 R16.1
N14849: C15.1 R12.1
N14853: C20.1 R17.1
N14855: C16.1 R13.1
N15143: C17.1 R14.1
N15151: C13.1 R10.1
N15155: C18.1 R15.1
N15161: C14.1 R11.1
N58063: U8.12 U14.19
N58118: U8.13 U14.18
N58173: U8.14 U14.17
N58228: U8.15 U14.16
N58283: U8.16 U14.15
N58338: U8.17 U14.14
N58393: U8.18 U14.13
N58448: U8.19 U14.12(Q8)
N58834: U11.12 U15.19
N58889: U11.13 U15.18
N58944: U11.14 U15.17
N58999: U11.15 U15.16
N59054: U11.16 U15.15
N59109: U11.17 U15.14
N59164: U11.18 U15.13
N59219: U11.19 U15.12(Q8)
N409523: R5.1 U5.37

Pads without a net: J1 12 48 49; U2 7; U5 16 27 35 36 52 55 72; U6 13 15 17 19; U7 6; U9 1 5 8; U12 1 5 8; U16 1 12 13 16 17; U17 1 12 13 16 17; U18 1 12 13 16 17; U19 1 12 13 16 17; U20 1 12 13 16 17; U21 1 12 13 16 17; U22 1 12 13 16 17; U23 1 12 13 16 17

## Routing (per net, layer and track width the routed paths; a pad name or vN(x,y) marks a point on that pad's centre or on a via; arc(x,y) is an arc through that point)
GND: length 57.9
  GND1 w0.4: 37.54,79.44 U2.13 ; U2.13 38.37,78.61 ; U2.13 38.37,80.27 ; U2.13 39.2,79.44 ; U7.5 22.25,105.12 ; U7.5 21.37,104.24 ; U7.5 21.37,106 ; U7.5 20.49,105.12 ; J1.33 12.08,21.47 ; J1.33 13.05,20.5 ; J1.33 12.08,19.53 ; J1.33 11.11,20.5 ; 6.03,20.5 J1.1 ; J1.1 7,19.53 ; J1.1 7.97,20.5 ; J1.1 7,21.47 ; 7,24.61 J1.3 ; J1.3 7.97,25.58 ; J1.3 6.03,25.58 ; J1.3 7,26.55 ; U2.11 46,77.73 ; U2.11 46.83,76.9 ; U2.11 45.17,76.9 ; U2.11 46,76.07 ; 7,22.07 J1.2 ; J1.2 7.97,23.04 ; J1.2 7,24.01 ; J1.2 6.03,23.04 ; U2.12 46.83,79.44 ; U2.12 46,78.61 ; U2.12 46,80.27 ; U2.12 45.17,79.44
  GND2 w0.4: 37.54,79.44 U2.13 ; U2.13 39.2,79.44 ; U2.13 38.37,78.61 ; U2.13 38.37,80.27 ; U2.11 46.83,76.9 ; U2.11 46,76.07 ; U2.11 46,77.73 ; U2.11 45.17,76.9 ; 46,78.61 U2.12 ; U2.12 46,80.27 ; U2.12 46.83,79.44 ; U2.12 45.17,79.44 ; J1.3 7.97,25.58 ; J1.3 7,26.55 ; J1.3 7,24.61 ; J1.3 6.03,25.58 ; 7,19.53 J1.1 ; J1.1 7,21.47 ; J1.1 6.03,20.5 ; J1.1 7.97,20.5 ; J1.2 7,24.01 ; J1.2 7.97,23.04 ; J1.2 7,22.07 ; J1.2 6.03,23.04 ; J1.33 13.05,20.5 ; J1.33 11.11,20.5 ; J1.33 12.08,21.47 ; J1.33 12.08,19.53 ; 21.37,104.24 U7.5 ; U7.5 22.25,105.12 ; U7.5 20.49,105.12 ; U7.5 21.37,106
VCC: length 88.6
  VCC1 w0.4: 12.08,93.19 J1.62 ; J1.62 11.11,94.16 ; J1.62 13.05,94.16 ; J1.62 12.08,95.13 ; U2.24 39.2,51.5 ; U2.24 38.37,52.33 ; U2.24 38.37,50.67 ; U2.24 37.54,51.5 ; D4.A 117.2,52.5 ; D4.A 116.27,53.43 ; D4.A 115.34,52.5 ; D4.A 116.27,51.57 ; 101.5,29.07 L4.1 ; L4.1 101.5,30.93 ; L4.1 102.43,30 ; L4.1 100.57,30 ; 21.37,96.62 U7.8 ; U7.8 20.49,97.5 ; U7.8 22.25,97.5 ; U7.8 21.37,98.38 ; J1.29 7.97,91.62 ; J1.29 7,92.59 ; J1.29 6.03,91.62 ; J1.29 7,90.65 ; 110.27,54.07 D3.A ; D3.A 111.2,55 ; D3.A 110.27,55.93 ; D3.A 109.34,55 ; D2.A 104.27,58.43 ; D2.A 103.34,57.5 ; D2.A 104.27,56.57 ; D2.A 105.2,57.5 ; L6.1 102.43,10.08 ; L6.1 101.5,9.15 ; L6.1 100.57,10.08 ; L6.1 101.5,11.01 ; U7.7 22.25,100.04 ; U7.7 20.49,100.04 ; U7.7 21.37,99.16 ; U7.7 21.37,100.92 ; 98.27,59.07 D1.A ; D1.A 98.27,60.93 ; D1.A 99.2,60 ; D1.A 97.34,60 ; 6.03,94.16 J1.30 ; J1.30 7,95.13 ; J1.30 7,93.19 ; J1.30 7.97,94.16
  VCC2 w0.4: D3.A 111.2,55 ; D3.A 110.27,54.07 ; D3.A 110.27,55.93 ; D3.A 109.34,55 ; 20.49,100.04 U7.7 ; U7.7 21.37,100.92 ; U7.7 21.37,99.16 ; U7.7 22.25,100.04 ; J1.29 7.97,91.62 ; J1.29 7,92.59 ; J1.29 6.03,91.62 ; J1.29 7,90.65 ; 100.57,30 L4.1 ; L4.1 102.43,30 ; L4.1 101.5,29.07 ; L4.1 101.5,30.93 ; U7.8 22.25,97.5 ; U7.8 21.37,98.38 ; U7.8 20.49,97.5 ; U7.8 21.37,96.62 ; 115.34,52.5 D4.A ; D4.A 116.27,51.57 ; D4.A 117.2,52.5 ; D4.A 116.27,53.43 ; J1.62 13.05,94.16 ; J1.62 11.11,94.16 ; J1.62 12.08,95.13 ; J1.62 12.08,93.19 ; D1.A 99.2,60 ; D1.A 97.34,60 ; D1.A 98.27,59.07 ; D1.A 98.27,60.93 ; 101.5,9.15 L6.1 ; L6.1 101.5,11.01 ; L6.1 102.43,10.08 ; L6.1 100.57,10.08 ; 104.27,56.57 D2.A ; D2.A 104.27,58.43 ; D2.A 103.34,57.5 ; D2.A 105.2,57.5 ; 38.37,50.67 U2.24 ; U2.24 39.2,51.5 ; U2.24 38.37,52.33 ; U2.24 37.54,51.5 ; 6.03,94.16 J1.30 ; J1.30 7,93.19 ; J1.30 7,95.13 ; J1.30 7.97,94.16

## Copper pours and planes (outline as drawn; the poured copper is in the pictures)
GND on GND1, GND2: 21,1.41 21,9 20.41,10.41 19,11 1.41,11 1,11.41 1,108.59 1.41,109 19,109 20.41,109.59 21,111 21,118.59 21.41,119 118.59,119 119,118.59 119,1.41 118.59,1 21.41,1 ; 2 cut-outs
VCC on VCC1, VCC2: 21,1.41 21,9 20.41,10.41 19,11 1.41,11 1,11.41 1,108.59 1.41,109 19,109 20.41,109.59 21,111 21,118.59 21.41,119 118.59,119 119,118.59 119,1.41 118.59,1 21.41,1 ; 2 cut-outs
